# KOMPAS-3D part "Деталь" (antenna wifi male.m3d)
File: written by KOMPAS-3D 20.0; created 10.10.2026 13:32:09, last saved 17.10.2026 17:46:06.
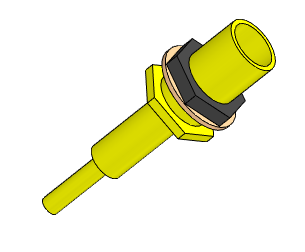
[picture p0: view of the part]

Document properties: Полное имя файла: D:\myProjects\Progect_esp32\box_compas\wifi\antenna wifi male.m3d

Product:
- Part/product: Деталь
    Масса: 0.00382422

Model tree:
1. Эскиз:1
2. Элемент выдавливания:1
     Расстояние 1 = 10
3. Эскиз:2  (with: Элемент выдавливания:1)
4. Элемент выдавливания:2
     Расстояние 1 = 1
5. Эскиз:3  (with: Элемент выдавливания:2)
6. Элемент выдавливания:3
     Расстояние 1 = 10
7. Эскиз:4  (with: Элемент выдавливания:3)
8. Элемент выдавливания:4
     Расстояние 1 = 8
9. Эскиз:5  (with: Элемент выдавливания:1)
10. Элемент выдавливания:5
     Расстояние 2 = 3
11. Эскиз:6  (with: Элемент выдавливания:5)
12. Элемент выдавливания:6
     Расстояние 2 = 5
13. Смещенная плоскость:2  (with: Элемент выдавливания:2)
     Расстояние = 2
14. Эскиз:9  (with: Элемент выдавливания:2)
15. Элемент выдавливания:9
     Расстояние 1 = 0.5
16. Эскиз:10  (with: Элемент выдавливания:9)
17. Элемент выдавливания:10
     Расстояние 1 = 1.5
